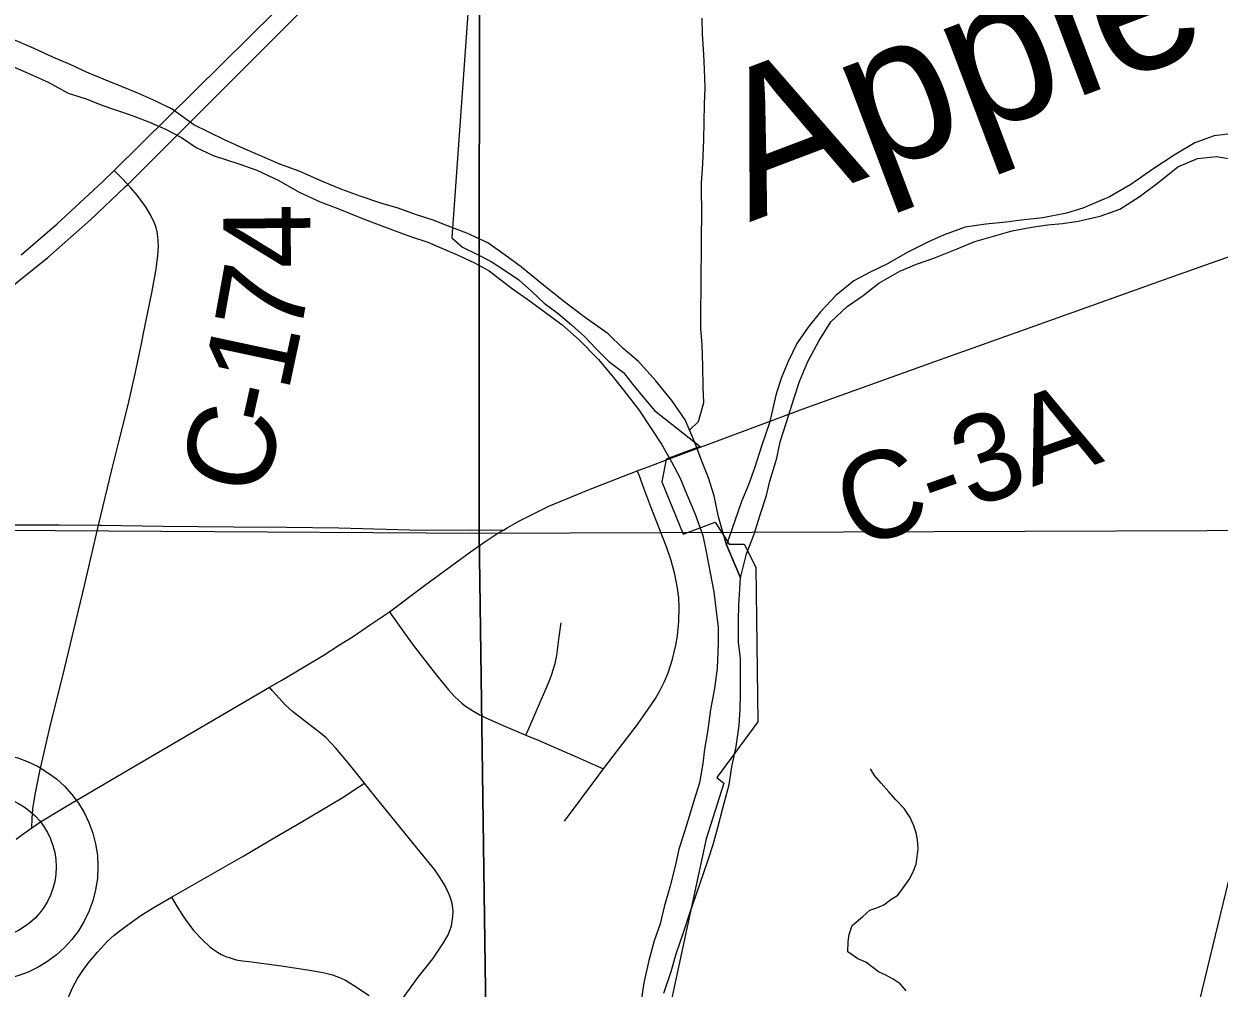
# Model space of a CAD drawing. Extents: x 0 to 34, y 0 to 22.
# Drawn here: x 7.485 to 8.265, y 19.588 to 20.217 of the extents above; entities that cross this region are included whole.
import ezdxf

# ---------------------------------------------------------------- set-up
doc = ezdxf.new("R2010")
doc.units = 0
for name, color, linetype in [('Default', 7, 'Continuous'), ('GM_X_County_Road', 7, 'Continuous'), ('GM_X_County_Road_Text', 7, 'Continuous'), ('GM_X_Major_River', 7, 'Continuous'), ('GM_X_Minor_River', 7, 'Continuous'), ('GM_X_Minor_River_Text', 7, 'Continuous'), ('GM_X_Rail_Line', 7, 'Continuous'), ('GM_X_Section', 7, 'Continuous'), ('GM_X_State_Route', 7, 'Continuous'), ('GM_X_Township_Road', 7, 'Continuous'), ('GM_X_Unincorporated', 7, 'Continuous')]:
    doc.layers.add(name, color=color, linetype=linetype)

msp = doc.modelspace()

# ---------------------------------------------------------------- linework, layer by layer
at = {"layer": 'Default'}
for points in [[(7.7825, 20.89996), (6.76299, 20.89996), (6.77985, 19.89133), (7.78202, 19.88507)], [(7.90355, 20.89996), (7.7825, 20.89996), (7.78202, 19.88507), (8.79094, 19.88871), (8.78918, 20.89915)]]:
    msp.add_lwpolyline(points, close=True, dxfattribs=at)
msp.add_lwpolyline([(7.78335, 20.3457), (7.76425, 20.07757), (7.7711, 20.07154), (7.78098, 20.06666), (7.78971, 20.06216), (7.79921, 20.05614), (7.80796, 20.05012), (7.81633, 20.04259), (7.82432, 20.03504), (7.83345, 20.02826), (7.84221, 20.02073), (7.85058, 20.01319), (7.85819, 20.00527), (7.86658, 19.99696), (7.87608, 19.98981), (7.88219, 19.98188), (7.88943, 19.9732), (7.89629, 19.96489), (7.9261, 19.94157), (7.90406, 19.93325), (7.90117, 19.91843), (7.91512, 19.8843), (7.93584, 19.89206), (7.94499, 19.87785), (7.95473, 19.87771), (7.96251, 19.86288), (7.96382, 19.7619), (7.93692, 19.72559), (7.9415, 19.72187), (7.93003, 19.68561), (7.90157, 19.55362)], dxfattribs=at)
at = {"layer": 'GM_X_County_Road'}
for p, q in [((7.92631, 19.94102), (7.99322, 19.96598)), ((7.90427, 19.9327), (7.92631, 19.94102))]:
    msp.add_line(p, q, dxfattribs=at)
for points in [[(7.55287, 20.11233), (7.54843, 20.11688), (7.54386, 20.12156)], [(7.56168, 20.00844), (7.56289, 20.01429), (7.56857, 20.04178), (7.5713, 20.05703), (7.57246, 20.06611), (7.57277, 20.07227), (7.57248, 20.07839), (7.57205, 20.0814), (7.57135, 20.08433), (7.57032, 20.08715), (7.56759, 20.09264), (7.56443, 20.09794), (7.559, 20.10546), (7.55488, 20.11026), (7.55287, 20.11233)], [(7.99322, 19.96598), (8.0791, 19.997), (8.18152, 20.03349), (8.22833, 20.05015), (8.26932, 20.06472), (8.28998, 20.0717)], [(7.53366, 19.89013), (7.54233, 19.92637), (7.54706, 19.94447), (7.55305, 19.96865), (7.55785, 19.98991), (7.56168, 20.00844)], [(7.79777, 19.88703), (7.80018, 19.88852), (7.80781, 19.89287), (7.81699, 19.89743), (7.8275, 19.90255), (7.85328, 19.91321), (7.88511, 19.92561)], [(7.88511, 19.92561), (7.89385, 19.92881), (7.90427, 19.9327)], [(7.25358, 19.90978), (7.25468, 19.90918), (7.26506, 19.90331), (7.2682, 19.90153), (7.27626, 19.89697), (7.27954, 19.89567), (7.28222, 19.8946), (7.28533, 19.89389), (7.29157, 19.89299), (7.30096, 19.89246), (7.32533, 19.89244), (7.35068, 19.89241), (7.38482, 19.8916), (7.42501, 19.89092), (7.4435, 19.89058), (7.45891, 19.89034), (7.47101, 19.89032), (7.47706, 19.89032), (7.508, 19.89034), (7.53366, 19.89013)], [(7.49011, 19.69284), (7.49049, 19.69893), (7.49088, 19.70524), (7.49229, 19.71454), (7.49546, 19.72982), (7.50183, 19.75716), (7.51143, 19.79653), (7.5246, 19.85084), (7.53366, 19.89013)], [(7.53366, 19.89013), (7.5357, 19.89015), (7.57566, 19.88957), (7.62207, 19.88908), (7.65625, 19.88879), (7.69042, 19.88838), (7.73684, 19.88726), (7.77679, 19.88698), (7.78912, 19.88706), (7.79777, 19.88703)], [(7.72344, 19.83379), (7.74634, 19.85082), (7.77639, 19.87289), (7.78577, 19.8794), (7.79423, 19.88488), (7.79777, 19.88703)], [(7.64521, 19.78447), (7.65333, 19.78923), (7.68015, 19.80531), (7.69093, 19.8122), (7.69978, 19.8177), (7.7112, 19.82534), (7.72279, 19.8333), (7.72344, 19.83379)], [(7.49011, 19.69284), (7.49576, 19.6968), (7.51171, 19.70641), (7.54618, 19.72645), (7.64521, 19.78447)], [(7.47997, 19.68554), (7.48424, 19.68873), (7.49011, 19.69284)]]:
    msp.add_lwpolyline(points, dxfattribs=at)
at = {"layer": 'GM_X_Major_River'}
for points in [[(7.94333, 19.87739), (7.93807, 19.8956), (7.93533, 19.90923), (7.93146, 19.92096), (7.9276, 19.93079), (7.92259, 19.94403), (7.91643, 19.95878), (7.90763, 19.9716), (7.89731, 19.98442), (7.88587, 19.99685), (7.87596, 20.0055), (7.86605, 20.0149), (7.85044, 20.02616), (7.83788, 20.03555), (7.82417, 20.04644), (7.80969, 20.05847), (7.79904, 20.06636), (7.78762, 20.07423), (7.77394, 20.08058), (7.76141, 20.08541), (7.75192, 20.08914), (7.74053, 20.09284), (7.72914, 20.09693), (7.71775, 20.10025), (7.70446, 20.10471), (7.69232, 20.10917), (7.67978, 20.11438), (7.66459, 20.12109), (7.65206, 20.12555), (7.62774, 20.13599), (7.61597, 20.14158), (7.60571, 20.14644), (7.59583, 20.15129), (7.58174, 20.16143), (7.5711, 20.16666), (7.55933, 20.17188), (7.54869, 20.17635), (7.53844, 20.18044), (7.5259, 20.18566), (7.51527, 20.19051), (7.50387, 20.19535), (7.49171, 20.20095), (7.47803, 20.20691)], [(7.47588, 20.19021), (7.49032, 20.18387), (7.50095, 20.17902), (7.51388, 20.17192), (7.52564, 20.16821), (7.5359, 20.16412), (7.54539, 20.16077), (7.55564, 20.15744), (7.56703, 20.15297), (7.57729, 20.1485), (7.58793, 20.14289), (7.59744, 20.13651), (7.60846, 20.13129), (7.62517, 20.12573), (7.63693, 20.12164), (7.65137, 20.11493), (7.66468, 20.10744), (7.67836, 20.1011), (7.68975, 20.09663), (7.7038, 20.09105), (7.7133, 20.08733), (7.72545, 20.08287), (7.73722, 20.07841), (7.7486, 20.0747), (7.7581, 20.0706), (7.76874, 20.06613), (7.779, 20.06127), (7.7885, 20.05603), (7.80373, 20.04439), (7.81363, 20.03726), (7.82353, 20.03013), (7.83609, 20.02075), (7.84714, 20.01097), (7.85972, 19.99817), (7.87042, 19.98535), (7.87844, 19.97518), (7.88608, 19.96537), (7.89412, 19.9533), (7.90101, 19.94311), (7.90753, 19.9314), (7.9129, 19.9212), (7.91752, 19.91024), (7.92291, 19.89739), (7.92793, 19.88339), (7.93028, 19.87165), (7.93264, 19.85915), (7.935, 19.84666), (7.9366, 19.83415), (7.93781, 19.82354), (7.93789, 19.81293), (7.93724, 19.79699), (7.93543, 19.78371), (7.93288, 19.77003), (7.93108, 19.75675), (7.92889, 19.74421), (7.92782, 19.73473), (7.92563, 19.72219), (7.92193, 19.71041), (7.91897, 19.70015), (7.91526, 19.68836), (7.9123, 19.67886), (7.9101, 19.66861), (7.90641, 19.65417), (7.90271, 19.64124)], [(7.95237, 19.85588), (7.94333, 19.87739)], [(7.90234, 19.58511), (7.90717, 19.59918), (7.9105, 19.61058), (7.91532, 19.62465), (7.9194, 19.6372), (7.92831, 19.66305), (7.93166, 19.67256), (7.93462, 19.68206), (7.93758, 19.69308), (7.9409, 19.70562), (7.94496, 19.7212), (7.94677, 19.73259), (7.94971, 19.74589), (7.95151, 19.75956), (7.95219, 19.77018), (7.9525, 19.78004), (7.95234, 19.80355), (7.95114, 19.81378), (7.95104, 19.82782), (7.95135, 19.83806), (7.95237, 19.85588)], [(7.90271, 19.64124), (7.90013, 19.63023), (7.89605, 19.6192), (7.89273, 19.60628), (7.88942, 19.59184), (7.8876, 19.58007)]]:
    msp.add_lwpolyline(points, dxfattribs=at)
at = {"layer": 'GM_X_Minor_River'}
msp.add_line((7.94333, 19.87739), (7.95237, 19.85588), dxfattribs=at)
for points in [[(7.91918, 19.9522), (7.92515, 19.9577), (7.92847, 19.97024), (7.92802, 19.9801), (7.92792, 19.99413), (7.92745, 20.00778), (7.92662, 20.01839), (7.92653, 20.03128), (7.92682, 20.0438), (7.92675, 20.0548), (7.92704, 20.06732), (7.92695, 20.08059), (7.92726, 20.09045), (7.9271, 20.11321), (7.92778, 20.12573), (7.92842, 20.14166), (7.92872, 20.15304), (7.92902, 20.1648), (7.92933, 20.17542), (7.92887, 20.18755), (7.92842, 20.19703), (7.92757, 20.21029), (7.9275, 20.22091)], [(8.2757, 20.14578), (8.26132, 20.14416), (8.24885, 20.13952), (8.23527, 20.13145), (8.22132, 20.12224), (8.207, 20.11228), (8.19304, 20.10421), (8.17567, 20.09687), (8.16509, 20.09376), (8.14958, 20.09061), (8.13558, 20.08898), (8.12574, 20.08777), (8.11249, 20.08653), (8.09887, 20.08454), (8.08527, 20.0795), (8.07508, 20.07488), (8.06111, 20.06795), (8.04828, 20.06064), (8.03696, 20.05525), (8.02639, 20.04948), (8.01472, 20.03991), (8.00457, 20.02922), (7.99668, 20.0193), (7.98918, 20.00862), (7.98358, 19.99682), (7.97911, 19.98655), (7.97577, 19.97591), (7.97136, 19.95691), (7.96616, 19.9417), (7.96171, 19.92802), (7.95762, 19.91661), (7.95315, 19.90558), (7.94869, 19.89303), (7.94333, 19.87739)], [(7.95237, 19.85588), (7.95642, 19.87147), (7.96125, 19.8844), (7.96496, 19.89618), (7.96941, 19.90949), (7.97162, 19.91899), (7.97606, 19.93381), (7.97826, 19.94445), (7.98234, 19.95737), (7.98753, 19.97334), (7.99087, 19.98398), (7.99646, 19.99692), (8.00356, 20.01025), (8.01143, 20.02282), (8.02197, 20.03276), (8.03252, 20.04005), (8.04269, 20.04809), (8.05627, 20.05577), (8.06722, 20.06041), (8.07856, 20.06428), (8.09367, 20.07046), (8.10538, 20.07511), (8.12957, 20.08211), (8.14243, 20.08448), (8.15264, 20.08608), (8.16248, 20.08691), (8.1727, 20.0885), (8.18707, 20.09164), (8.19991, 20.09629), (8.21236, 20.10435), (8.22442, 20.11316), (8.2376, 20.12388), (8.25044, 20.12929), (8.26293, 20.13052), (8.2762, 20.12834)], [(8.06039, 19.58661), (8.05653, 19.59112), (8.05193, 19.5941), (8.04733, 19.5967), (8.04236, 19.59891), (8.03429, 19.60526), (8.02893, 19.60747), (8.02241, 19.61194), (8.0227, 19.61878), (8.0234, 19.62335), (8.02523, 19.62907), (8.032, 19.63486), (8.03689, 19.6391), (8.04143, 19.64068), (8.04597, 19.64264), (8.05049, 19.64612), (8.05502, 19.64884), (8.05913, 19.65459), (8.06249, 19.6592), (8.06509, 19.66417), (8.06693, 19.66913), (8.06762, 19.67408), (8.06832, 19.6794), (8.06786, 19.6851), (8.06704, 19.68964), (8.06546, 19.69418), (8.06311, 19.69947), (8.05923, 19.70549), (8.05383, 19.71112), (8.0492, 19.71638), (8.04418, 19.72201), (8.03993, 19.72689), (8.03721, 19.73141)]]:
    msp.add_lwpolyline(points, dxfattribs=at)
at = {"layer": 'GM_X_Rail_Line'}
msp.add_lwpolyline([(7.41554, 16.97974), (7.45576, 17.1778), (7.51777, 17.49987), (7.54259, 17.62251), (7.57169, 17.70433), (7.63213, 17.85839), (7.88249, 18.49369), (8.02356, 18.85844), (8.15149, 19.17223), (8.16753, 19.23137), (8.32815, 19.89453)], dxfattribs=at)
at = {"layer": 'GM_X_Section'}
for points in [[(6.77985, 19.89133), (7.78202, 19.88507), (7.79585, 18.88307), (6.78469, 18.87524)], [(7.78202, 19.88507), (8.79094, 19.88871), (8.79603, 18.89006), (7.79585, 18.88307)]]:
    msp.add_lwpolyline(points, close=True, dxfattribs=at)
at = {"layer": 'GM_X_State_Route'}
for points in [[(7.48316, 20.06646), (7.50668, 20.08673), (7.53629, 20.11415), (7.54386, 20.12156), (7.66658, 20.24273), (7.71121, 20.28587), (7.77761, 20.35137)], [(7.47177, 20.04139), (7.5007, 20.06483), (7.52864, 20.08944), (7.55119, 20.11074), (7.55287, 20.11233), (7.66324, 20.22268), (7.71096, 20.27161), (7.78356, 20.34515)]]:
    msp.add_lwpolyline(points, dxfattribs=at)
at = {"layer": 'GM_X_Township_Road'}
for points in [[(7.86311, 19.73133), (7.86946, 19.7396), (7.88454, 19.75938), (7.89182, 19.76947), (7.89694, 19.77727), (7.90007, 19.78266), (7.90285, 19.78822), (7.90521, 19.79397), (7.90807, 19.80287), (7.91033, 19.81193), (7.91133, 19.81806), (7.91223, 19.82736), (7.91253, 19.83669), (7.91218, 19.8429), (7.91139, 19.84907), (7.90953, 19.85822), (7.90711, 19.86724), (7.90416, 19.87609), (7.89406, 19.90222), (7.88947, 19.91434), (7.8863, 19.9227), (7.88511, 19.92561)], [(7.72344, 19.83379), (7.72486, 19.83175), (7.7317, 19.82191), (7.73904, 19.81198), (7.7541, 19.79238), (7.76193, 19.78285), (7.76611, 19.77831), (7.77063, 19.77412), (7.77307, 19.77223), (7.77825, 19.76888), (7.78244, 19.7665), (7.78643, 19.76455), (7.79768, 19.75948), (7.81246, 19.75327)], [(7.81246, 19.75327), (7.81432, 19.75754), (7.82621, 19.78479), (7.82823, 19.78999), (7.82946, 19.79309), (7.83029, 19.79594), (7.83152, 19.8), (7.83259, 19.80523), (7.83422, 19.8174), (7.83539, 19.82653)], [(7.70717, 19.72186), (7.6965, 19.73518), (7.68854, 19.74471), (7.68213, 19.75144), (7.67745, 19.75549), (7.67006, 19.76116), (7.66024, 19.76875), (7.65564, 19.77289), (7.65145, 19.77743), (7.64726, 19.78216), (7.64521, 19.78447)], [(7.81246, 19.75327), (7.82043, 19.74993), (7.8459, 19.73896), (7.85764, 19.73376), (7.86311, 19.73133)], [(7.83773, 19.69729), (7.85999, 19.72727), (7.86311, 19.73133)], [(7.5814, 19.64764), (7.59345, 19.65458), (7.62847, 19.67449), (7.64984, 19.68709), (7.66582, 19.69662), (7.69257, 19.71232), (7.70295, 19.71911), (7.70717, 19.72186)], [(7.72608, 19.57292), (7.73473, 19.58532), (7.74214, 19.59535), (7.75168, 19.60752), (7.7553, 19.61256), (7.75869, 19.61774), (7.7617, 19.62316), (7.76293, 19.62599), (7.76385, 19.62893), (7.76445, 19.63195), (7.76484, 19.63504), (7.765, 19.63812), (7.7649, 19.64043), (7.76438, 19.64345), (7.76355, 19.64643), (7.76245, 19.64933), (7.75976, 19.65492), (7.75664, 19.66028), (7.7531, 19.66536), (7.74137, 19.67979), (7.71396, 19.7134), (7.70717, 19.72186)], [(7.50086, 19.53661), (7.50209, 19.54184), (7.50352, 19.54787), (7.50753, 19.56285), (7.51123, 19.57469), (7.51448, 19.5834), (7.51706, 19.58904), (7.52002, 19.59448), (7.52337, 19.5997), (7.52706, 19.60469), (7.53302, 19.61184), (7.53938, 19.61863), (7.54393, 19.62283), (7.55124, 19.62857), (7.56141, 19.63569), (7.56927, 19.64065), (7.5814, 19.64764)], [(7.5814, 19.64764), (7.58495, 19.64138), (7.58794, 19.63664), (7.59027, 19.6333), (7.59261, 19.62994), (7.59563, 19.62593), (7.60175, 19.61948), (7.60627, 19.61531), (7.6087, 19.61342), (7.61126, 19.61173), (7.61396, 19.61027), (7.61677, 19.60904), (7.61968, 19.60807), (7.62359, 19.60684), (7.62754, 19.60618), (7.6317, 19.6056), (7.65301, 19.60279), (7.67125, 19.60013), (7.68031, 19.59842), (7.68629, 19.59698), (7.6892, 19.596), (7.69203, 19.59482), (7.69477, 19.59344), (7.70004, 19.59029), (7.71023, 19.58342)]]:
    msp.add_lwpolyline(points, dxfattribs=at)
at = {"layer": 'GM_X_Unincorporated'}
for radius in [0.0744, 0.04716]:
    msp.add_circle((7.45894, 19.66733), radius, dxfattribs=at)

# ---------------------------------------------------------------- texts
at = {"layer": 'GM_X_County_Road_Text'}
for s, height, rotation, p in [('4', 0.05682, 90.48034, (7.67213, 20.05774)), ('7', 0.05682, 79.76793, (7.66498, 20.01203)), ('1', 0.05682, 77.95615, (7.65736, 19.97614)), ('-', 0.05682, 77.33709, (7.65214, 19.95293)), ('C-3A', 0.056818, 19.61219, (8.02743, 19.87394)), ('C', 0.05682, 77.23235, (7.64188, 19.90764))]:
    msp.add_text(s, height=height, rotation=rotation, dxfattribs=at).set_placement(p)
at = {"layer": 'GM_X_Minor_River_Text'}
msp.add_text('Apple', height=0.094723, rotation=20.76282, dxfattribs=at).set_placement((7.95818, 20.08769))

doc.saveas('drawing.dxf')
